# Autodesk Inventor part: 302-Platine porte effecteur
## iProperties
Author: Philippe
Shininess: 20.0
Angle Display Precision: 2
Document Length Units: 11269
Document Angle Units: 11283
Document Time Units: 11279
Document Mass Units: 11290
Document Length Units Precision: 3
Document Angle Units Precision: 2
Compacted: False
PropertySet Name: _Private Model Information
Created: 2001-12
Part Number: 302-Platine porte effecteur
Material: Par défaut
Document SubType Name: Modélisation
Designer: Philippe
Control State: 0
Master: False
Checked Out: False
PropertySet Name: Design Tracking Control
Density: 0.0
Volumn: 0.0
Area: 0.0
PropertySet Name: Model Information
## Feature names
1. Extrusion1
2. Extrusion2
3. Extrusion3
4. Extrusion4
5. Extrusion5
6. Extrusion6
7. Extrusion7
8. Extrusion8
9. Extrusion9
10. Symétrie1 [Mirror]
